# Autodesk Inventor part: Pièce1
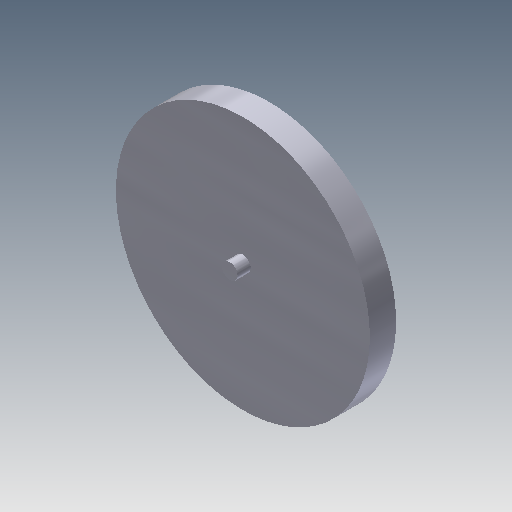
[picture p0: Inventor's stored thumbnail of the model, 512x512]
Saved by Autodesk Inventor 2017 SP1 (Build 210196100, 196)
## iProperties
Created: 2013-05
Part Number: Pièce1
Material: Générique
Document SubType Name: Modeling
Designer: jost thierry
Density: 1 g/cm^3
Mass: 74.1809 g
Surface Area: 180.155 cm^2
Volume: 74.1809 cm^3
Appearance: Blanc froid
Author: jost thierry
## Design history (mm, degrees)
sketch "Esquisse1"
  geometry: C1 r 48.5 at (0, 0); 1 further point
  constraints: 1 centre point, 1 coincident
  dimensions: "d0" = 97 diameter of C1
extrude "Extrusion1" new body sketch "Esquisse1" stored distance "d1" = 10; taper "d2" = 0 deg
sketch "Esquisse2"
  geometry: C1 r 48.5 at (0, 0) reference; C2 r 3 at (0, 0)
  constraints: 1 centre point, 1 coincident
  dimensions: "d3" = 6 diameter of C2
extrude "Extrusion2" join sketch "Esquisse2" distance "d4" = 5; taper "d6" = 0 deg; dims "d5" = 15, "d7" = 0
node "Solide1"
